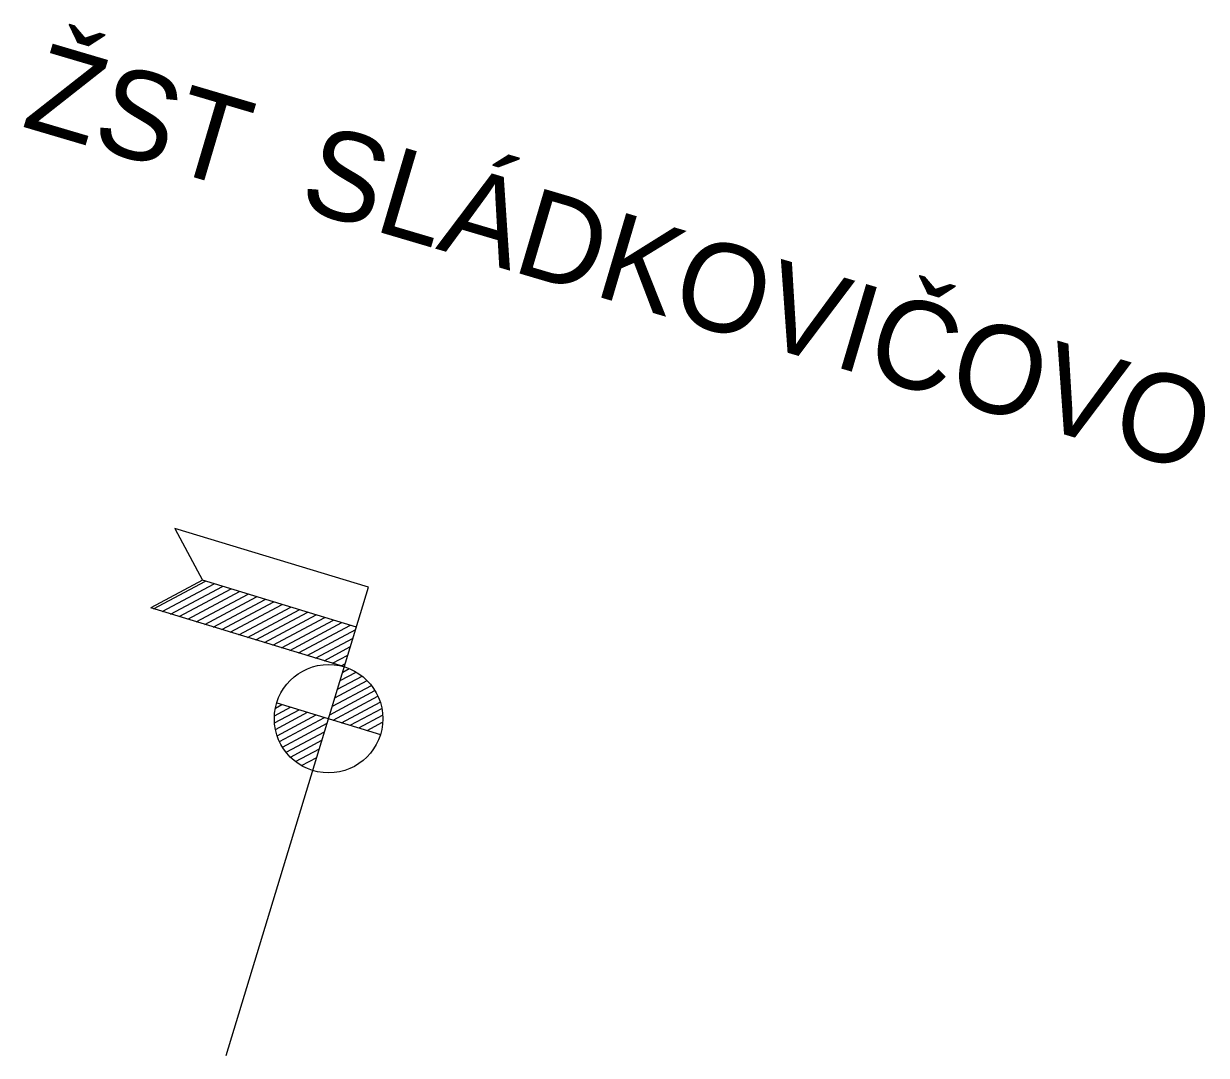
# Model space of a CAD drawing. Extents: x -566241 to -448637, y -1329577 to -1274522.
# Drawn here: x -534716 to -533777, y -1278905 to -1278085 of the extents above; entities that cross this region are included whole.
import ezdxf

# ---------------------------------------------------------------- set-up
doc = ezdxf.new("R2010")
doc.units = 0
doc.layers.add('DOPRAVNE', color=7, linetype='Continuous')
doc.layers.add('DOPRAVNE NAZOV', color=7, linetype='Continuous')

msp = doc.modelspace()

# ---------------------------------------------------------------- linework, layer by layer
at = {"layer": 'DOPRAVNE'}
for p, q in [((-534596.05, -1278486.33), (-534574.07, -1278527.52)), ((-534442.33, -1278533.09), (-534596.05, -1278486.33)), ((-534574.07, -1278527.52), (-534615.27, -1278549.5)), ((-534612.96, -1278550.2), (-534571.76, -1278528.23)), ((-534606.19, -1278552.26), (-534565, -1278530.28)), ((-534451.94, -1278564.68), (-534574.07, -1278527.52)), ((-534599.43, -1278554.32), (-534558.23, -1278532.34)), ((-534592.66, -1278556.38), (-534551.47, -1278534.4)), ((-534585.9, -1278558.43), (-534544.7, -1278536.46)), ((-534579.13, -1278560.49), (-534537.94, -1278538.52)), ((-534572.37, -1278562.55), (-534531.17, -1278540.57)), ((-534555.39, -1278904.75), (-534442.33, -1278533.09)), ((-534461.55, -1278596.26), (-534615.27, -1278549.5)), ((-534565.6, -1278564.61), (-534524.41, -1278542.63)), ((-534558.84, -1278566.67), (-534517.64, -1278544.69)), ((-534552.07, -1278568.72), (-534510.88, -1278546.75)), ((-534545.31, -1278570.78), (-534504.11, -1278548.8)), ((-534538.54, -1278572.84), (-534497.35, -1278550.86)), ((-534531.78, -1278574.9), (-534490.58, -1278552.92)), ((-534525.01, -1278576.96), (-534483.82, -1278554.98)), ((-534518.25, -1278579.01), (-534477.05, -1278557.04)), ((-534511.48, -1278581.07), (-534470.29, -1278559.09)), ((-534504.72, -1278583.13), (-534463.52, -1278561.15)), ((-534497.95, -1278585.19), (-534456.76, -1278563.21)), ((-534491.19, -1278587.25), (-534452.53, -1278566.62)), ((-534484.42, -1278589.3), (-534454.59, -1278573.39)), ((-534477.66, -1278591.36), (-534456.65, -1278580.15)), ((-534477.66, -1278591.36), (-534456.65, -1278580.15)), ((-534470.89, -1278593.42), (-534458.71, -1278586.92)), ((-534470.89, -1278593.42), (-534458.71, -1278586.92)), ((-534464.13, -1278595.48), (-534460.76, -1278593.68)), ((-534464.13, -1278595.48), (-534460.76, -1278593.68)), ((-534466.94, -1278613.98), (-534447.48, -1278603.6)), ((-534464.88, -1278607.21), (-534452.13, -1278600.41)), ((-534462.82, -1278600.45), (-534457.62, -1278597.67)), ((-534473.11, -1278634.27), (-534437.26, -1278615.15)), ((-534471.05, -1278627.51), (-534440.12, -1278611)), ((-534469, -1278620.74), (-534443.51, -1278607.14)), ((-534515.23, -1278624.9), (-534432.91, -1278649.94)), ((-534470.45, -1278638.52), (-534434.93, -1278619.57)), ((-534463.69, -1278640.58), (-534433.11, -1278624.26)), ((-534517.02, -1278635.03), (-534504.28, -1278628.23)), ((-534516.97, -1278640.67), (-534497.51, -1278630.29)), ((-534516.25, -1278628.95), (-534511.04, -1278626.17)), ((-534516.23, -1278645.94), (-534490.75, -1278632.35)), ((-534514.92, -1278650.91), (-534483.98, -1278634.4)), ((-534456.92, -1278642.64), (-534431.83, -1278629.25)), ((-534450.16, -1278644.69), (-534431.15, -1278634.55)), ((-534513.06, -1278655.59), (-534477.22, -1278636.46)), ((-534510.69, -1278659.99), (-534475.17, -1278641.04)), ((-534443.39, -1278646.75), (-534431.14, -1278640.22)), ((-534507.8, -1278664.11), (-534477.23, -1278647.8)), ((-534504.37, -1278667.95), (-534479.29, -1278654.57)), ((-534500.35, -1278671.47), (-534481.34, -1278661.33)), ((-534495.65, -1278674.63), (-534483.4, -1278668.1))]:
    msp.add_line(p, q, dxfattribs=at)
msp.add_circle((-534474.07, -1278637.42), 43.02, dxfattribs=at)

# ---------------------------------------------------------------- texts
at = {"layer": 'DOPRAVNE NAZOV'}
msp.add_text('ŽST  SLÁDKOVIČOVO', height=70, rotation=343.53299, dxfattribs=at).set_placement((-534718.95, -1278166.71))

doc.saveas('drawing.dxf')
